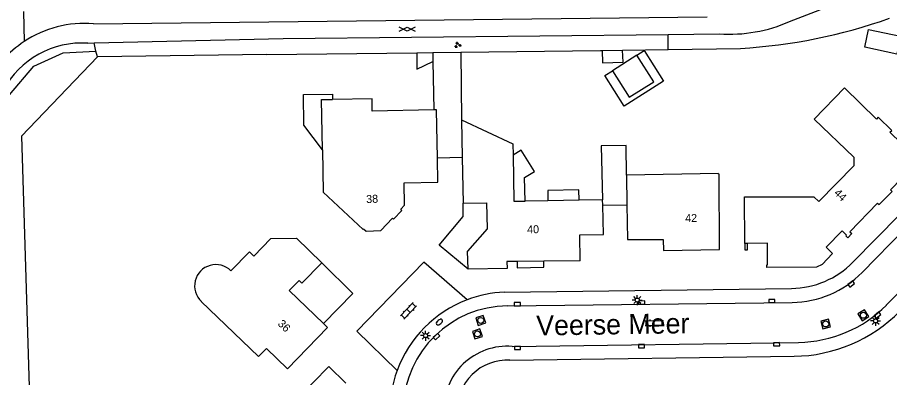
# Model space of a CAD drawing. Extents: x 128999 to 131010, y 395498 to 399007.
# Drawn here: x 130797.9 to 130906.8, y 395862.2 to 395907.2 of the extents above; entities that cross this region are included whole.
import ezdxf

# ---------------------------------------------------------------- set-up
doc = ezdxf.new("R2010")
doc.units = 0
for name, color, linetype in [('gg-afsc-hekwerk', 7, 'Continuous'), ('gg-afsc-muur', 7, 'Continuous'), ('gg-anno-huisnummerreeks BGT', 7, 'Continuous'), ('gg-anno-openbare ruimte label', 7, 'Continuous'), ('gg-bbg-gedigitaliseerde bebouwing', 7, 'Continuous'), ('gg-bbg-gedigitaliseerde bijgebouw', 7, 'Continuous'), ('gg-bbg-hoofdgebouw', 7, 'Continuous'), ('gg-bbg-luifel en loopbrug', 7, 'Continuous'), ('gg-knt-verharding', 7, 'Continuous'), ('gt-grn-groengrens', 7, 'Continuous'), ('gt-symb-brandkraan', 7, 'Continuous'), ('gt-symb-gesloten verharding', 7, 'Continuous'), ('gt-symb-groenvak', 7, 'Continuous'), ('gt-symb-klinker verharding', 7, 'Continuous'), ('gt-symb-kolk', 7, 'Continuous'), ('gt-symb-lichtmast', 7, 'Continuous'), ('gt-symb-rioolschacht', 7, 'Continuous')]:
    doc.layers.add(name, color=color, linetype=linetype)

# ---------------------------------------------------------------- blocks, each defined once
blk = doc.blocks.new('gt0-GRVAK')
at = {"layer": 'gt-symb-groenvak'}
for p, q in [((-0.11, 0.19), (-0.23, 0.24)), ((-0.18, 0.15), (0.09, 0.15)), ((-0.09, 0.21), (-0.16, 0.32)), ((-0.05, 0.21), (-0.05, 0.39)), ((0, 0.21), (0.06, 0.32)), ((0.01, 0.19), (0.13, 0.24)), ((0.26, -0.05), (0.2, 0.06)), ((0.31, -0.05), (0.31, 0.13)), ((0.35, -0.05), (0.41, 0.06)), ((-0.24, -0.23), (-0.36, -0.18)), ((-0.32, -0.26), (-0.05, -0.26)), ((-0.23, -0.21), (-0.29, -0.1)), ((-0.18, -0.2), (-0.18, -0.02)), ((-0.14, -0.21), (-0.07, -0.1)), ((-0.12, -0.23), (0, -0.18)), ((0.24, -0.07), (0.12, -0.02)), ((0.17, -0.11), (0.44, -0.11)), ((0.37, -0.07), (0.49, -0.02))]:
    blk.add_line(p, q, dxfattribs=at)
blk = doc.blocks.new('gt0-GESVH1')
at = {"layer": 'gt-symb-gesloten verharding'}
for p, q in [((-0.99, -0.26), (0.01, 0.24)), ((0.01, -0.26), (-0.99, 0.24)), ((0.01, 0.24), (1.01, -0.26)), ((1.01, 0.24), (0.01, -0.26))]:
    blk.add_line(p, q, dxfattribs=at)
blk = doc.blocks.new('gt0-RS')
at = {"layer": 'gt-symb-rioolschacht'}
blk.add_lwpolyline([(-0.5, -0.5), (0.5, -0.5), (0.5, 0.5), (-0.5, 0.5)], close=True, dxfattribs=at)
blk.add_circle((0, 0), 0.375, dxfattribs=at)
blk = doc.blocks.new('gt0-KOLK')
at = {"layer": 'gt-symb-kolk'}
blk.add_lwpolyline([(0, 0), (0.38, 0), (0.38, 0.4), (-0.38, 0.4), (-0.38, 0), (0, 0)], dxfattribs=at)
blk = doc.blocks.new('gt0-LMAST')
at = {"layer": 'gt-symb-lichtmast'}
for p, q in [((-0.18, 0.17), (-0.45, 0.44)), ((-0.01, 0.25), (-0.01, 0.62)), ((0.17, 0.17), (0.44, 0.44)), ((-0.26, 0), (-0.63, 0)), ((-0.18, -0.18), (-0.45, -0.45)), ((-0.01, -0.25), (-0.01, -0.63)), ((0.44, -0.45), (0.17, -0.18)), ((0.24, 0), (0.62, 0))]:
    blk.add_line(p, q, dxfattribs=at)
blk.add_circle((-0.01, 0), 0.25, dxfattribs=at)
blk = doc.blocks.new('gt0-KL1')
at = {"layer": 'gt-symb-klinker verharding'}
for p, q in [((-1.15, 0.3), (1.15, 0.3)), ((-1, -0.3), (-1, 0.3)), ((-0.5, 0.3), (-0.5, 0.45)), ((0, -0.3), (0, 0.3)), ((0.5, 0.3), (0.5, 0.45)), ((1, -0.3), (1, 0.3)), ((-1.15, -0.3), (1.15, -0.3)), ((-0.5, -0.45), (-0.5, -0.3)), ((0.5, -0.45), (0.5, -0.3))]:
    blk.add_line(p, q, dxfattribs=at)
blk = doc.blocks.new('gt0-BR')
at = {"layer": 'gt-symb-brandkraan'}
for centre, radius, start, end in [((-0.24, 0), 0.206, 107.5669, 252.4331), ((0.6, -2.66), 3, 106.892, 107.5669), ((0, -0.69), 0.938, 73.108, 106.892), ((-0.6, -2.66), 3, 72.4331, 73.108), ((0.24, 0), 0.206, 287.567, 72.4331), ((0.6, 2.66), 3, 252.4331, 253.108), ((0, 0.69), 0.938, 253.108, 286.8921), ((-0.6, 2.66), 3, 286.8921, 287.567)]:
    blk.add_arc(centre, radius, start, end, dxfattribs=at)

msp = doc.modelspace()

# ---------------------------------------------------------------- linework, layer by layer
at = {"layer": 'gg-afsc-hekwerk'}
for p, q in [((130829.04, 395902.55), (130807.85, 395902.25)), ((130870.72, 395903.06), (130870.93, 395903.07)), ((130873.49, 395903.1), (130879.19, 395903.18)), ((130879.19, 395903.18), (130888.21, 395903.32))]:
    msp.add_line(p, q, dxfattribs=at)
msp.add_lwpolyline([(130807.85, 395902.25), (130798.36, 395892.34), (130799.36, 395859.62)], dxfattribs=at)
msp.add_arc((130884.25, 395970.81), 67.61, 273.3578, 289.521, dxfattribs=at)
at = {"layer": 'gg-afsc-muur'}
for p, q in [((130829.04, 395902.55), (130847.75, 395902.78)), ((130853.28, 395902.85), (130870.72, 395903.06))]:
    msp.add_line(p, q, dxfattribs=at)
msp.add_lwpolyline([(130888.76, 395878.92), (130888.77, 395878.14), (130889.09, 395878.14), (130889.09, 395878.92)], dxfattribs=at)
at = {"layer": 'gg-bbg-gedigitaliseerde bebouwing'}
for p, q in [((130853.37, 395894.39), (130853.42, 395889.67)), ((130853.42, 395889.67), (130853.54, 395883.97)), ((130902.36, 395888.65), (130898, 395884.16)), ((130873.97, 395887.47), (130874.03, 395883.78)), ((130864.15, 395884.28), (130861.29, 395884.24)), ((130868.05, 395884.33), (130864.15, 395884.28)), ((130870.99, 395884.38), (130868.05, 395884.33)), ((130871.01, 395883.73), (130870.99, 395884.38)), ((130871.1, 395880.07), (130871.01, 395883.73)), ((130874.03, 395883.78), (130874.11, 395879.42)), ((130827.99, 395864.79), (130820.84, 395871.68))]:
    msp.add_line(p, q, dxfattribs=at)
for points in [[(130905.44, 395894.72), (130905.21, 395894.48), (130901.2, 395898.37), (130897.43, 395894.49), (130902.36, 395889.7), (130902.36, 395888.65)], [(130836, 395890.63), (130835.87, 395896.91), (130837.23, 395896.94)], [(130853.37, 395894.39), (130859.77, 395891.38), (130859.8, 395889.97)], [(130859.8, 395889.97), (130859.91, 395884.22), (130861.29, 395884.24)], [(130885.61, 395878.17), (130885.53, 395887.61), (130885.48, 395887.61), (130885.48, 395887.66), (130873.97, 395887.47)], [(130853.54, 395883.97), (130856.49, 395884.03), (130856.56, 395880.78), (130854.09, 395877.95)], [(130888.71, 395884.78), (130897.36, 395884.78), (130898, 395884.16)], [(130824.53, 395875.51), (130826.84, 395877.88), (130827.4, 395877.34), (130829.51, 395879.55), (130832.72, 395879.6)]]:
    msp.add_lwpolyline(points, dxfattribs=at)
msp.add_arc((130822.66, 395873.63), 2.66, 45.2051, 226.9895, dxfattribs=at)
at = {"layer": 'gg-bbg-gedigitaliseerde bijgebouw'}
msp.add_line((130875.28, 395902.47), (130872.21, 395900.53), dxfattribs=at)
for points in [[(130903.75, 395903.45), (130904.22, 395905.68), (130908.22, 395904.85), (130907.75, 395902.61), (130903.75, 395903.45)], [(130872.21, 395900.53), (130874.32, 395897.2), (130877.39, 395899.14), (130875.28, 395902.47)]]:
    msp.add_lwpolyline(points, dxfattribs=at)
at = {"layer": 'gg-bbg-hoofdgebouw'}
for p, q in [((130888.76, 395878.92), (130888.71, 395884.78)), ((130832.72, 395879.6), (130835.88, 395876.51)), ((130889.09, 395878.92), (130888.76, 395878.92)), ((130854.18, 395875.74), (130854.09, 395877.95)), ((130863.64, 395876.73), (130860.3, 395876.68)), ((130868.16, 395876.78), (130863.64, 395876.73))]:
    msp.add_line(p, q, dxfattribs=at)
for points in [[(130849.88, 395895.64), (130842.2, 395895.49), (130842.18, 395897.01), (130837.23, 395896.94)], [(130850.34, 395889.61), (130850.22, 395895.64), (130849.88, 395895.64)], [(130901.89, 395880.4), (130905.35, 395883.99), (130905.56, 395883.79), (130907.17, 395885.42), (130906.95, 395885.63), (130909.79, 395888.54), (130909.63, 395888.68), (130908.84, 395888.68), (130908.83, 395889.89), (130909.62, 395889.89), (130909.77, 395890.04), (130906.89, 395892.83), (130907.12, 395893.07), (130905.44, 395894.72)], [(130836, 395890.63), (130836.05, 395885.36), (130841.07, 395880.69), (130841.12, 395880.75), (130841.42, 395880.48), (130843.28, 395880.54), (130844.72, 395882.08), (130844.86, 395881.95), (130845.91, 395883.07), (130845.76, 395883.21), (130846.24, 395883.7), (130846.17, 395886.51), (130850.4, 395886.6), (130850.34, 395889.61)], [(130868.16, 395876.78), (130868.12, 395880.03), (130871.1, 395880.07)], [(130901.89, 395880.4), (130902.12, 395880.16), (130901.62, 395879.65), (130901.37, 395879.9), (130901.45, 395879.98), (130900.91, 395880.51), (130898.91, 395878.46), (130899.7, 395877.66), (130898.43, 395876.3), (130897.71, 395875.99)], [(130874.11, 395879.42), (130878.54, 395879.43), (130878.58, 395878.06), (130885.61, 395878.17)], [(130897.71, 395875.99), (130891.49, 395875.94), (130891.49, 395876.27), (130891.61, 395876.27), (130891.59, 395878.95), (130889.09, 395878.92)], [(130835.88, 395876.51), (130833.41, 395873.98), (130833.05, 395874.32), (130831.82, 395873.04), (130836.1, 395868.93)], [(130860.3, 395876.68), (130859.03, 395876.67), (130859.04, 395875.8), (130854.18, 395875.74)], [(130836.1, 395868.93), (130836.62, 395868.43), (130831.6, 395863.26), (130828.98, 395865.8), (130827.99, 395864.79)]]:
    msp.add_lwpolyline(points, dxfattribs=at)
at = {"layer": 'gg-bbg-luifel en loopbrug'}
for p, q in [((130847.75, 395902.78), (130849.75, 395902.8)), ((130849.75, 395902.8), (130853.28, 395902.85)), ((130849.75, 395902.8), (130849.77, 395901.69)), ((130853.28, 395902.85), (130853.37, 395894.39)), ((130870.93, 395903.07), (130873.49, 395903.1)), ((130849.77, 395901.69), (130849.88, 395895.64)), ((130853.42, 395889.67), (130850.34, 395889.61)), ((130871.01, 395883.73), (130874.03, 395883.78))]:
    msp.add_line(p, q, dxfattribs=at)
for points in [[(130847.75, 395902.78), (130847.79, 395900.72), (130849.77, 395901.69)], [(130870.93, 395903.07), (130870.98, 395901.5), (130873.55, 395901.59), (130873.49, 395903.1)], [(130875.28, 395902.47), (130876.17, 395903.04), (130878.6, 395899.21), (130873.68, 395896.1), (130871.26, 395899.92), (130872.21, 395900.53)], [(130836, 395890.63), (130833.66, 395893.74), (130833.61, 395897.57), (130837.22, 395897.61), (130837.23, 395896.94)], [(130861.29, 395884.24), (130861.23, 395887.17), (130862.46, 395887.94), (130860.8, 395890.6), (130859.8, 395889.97)], [(130873.97, 395887.47), (130873.91, 395891.17), (130870.82, 395891.12), (130870.99, 395884.38)], [(130868.05, 395884.33), (130868.03, 395885.62), (130864.12, 395885.55), (130864.15, 395884.28)], [(130854.18, 395875.74), (130850.55, 395878.7), (130853.58, 395882.3), (130853.54, 395883.97)], [(130835.88, 395876.51), (130839.78, 395872.68), (130836.1, 395868.93)], [(130860.3, 395876.68), (130860.32, 395875.89), (130863.65, 395875.95), (130863.64, 395876.73)], [(130838.91, 395861.49), (130836.78, 395863.56), (130832.87, 395859.54), (130834.99, 395857.47)]]:
    msp.add_lwpolyline(points, dxfattribs=at)
at = {"layer": 'gg-knt-verharding'}
for p, q in [((130894.36, 395906.67), (130903.75, 395910.33)), ((130807.36, 395906.39), (130884.04, 395907.27)), ((130879.17, 395905.07), (130885.59, 395905.13)), ((130806.64, 395903.97), (130807.44, 395903.99)), ((130903.41, 395875.3), (130908.72, 395880.71)), ((130906.44, 395871.23), (130912.33, 395877.16)), ((130858.71, 395872.86), (130894.59, 395873.3)), ((130859.14, 395871.13), (130894.67, 395871.57)), ((130859.67, 395866.07), (130895.46, 395866.57)), ((130859.41, 395864.33), (130894.91, 395864.83))]:
    msp.add_line(p, q, dxfattribs=at)
for points in [[(130807.44, 395903.99), (130831.07, 395904.56), (130879.17, 395905.07)], [(130902.26, 395876.58), (130910.99, 395885.48), (130918.09, 395892.81)], [(130854.06, 395871.89), (130848.63, 395876.58), (130840.26, 395867.98), (130845.3, 395863.04)]]:
    msp.add_lwpolyline(points, dxfattribs=at)
for centre, radius, start, end in [((130806.25, 395892.72), 13.72, 85.3839, 123.4647), ((130886.84, 395923.78), 18.69, 266.1683, 293.7172), ((130806.26, 395892.72), 13.72, 123.4836, 152.7203), ((130805.95, 395892.8), 11.19, 86.4746, 151.6318), ((130894.45, 395884.25), 10.94, 270.7206, 315.516), ((130894.52, 395884.03), 12.46, 270.7135, 315.5141), ((130859.41, 395857.88), 15, 92.672, 110.9029), ((130859.41, 395857.85), 15.03, 110.8661, 159.7976), ((130859.22, 395857.96), 13.17, 90.3847, 177.9885), ((130895.25, 395882.34), 15.77, 270.7853, 315.2259), ((130894.65, 395883.81), 18.98, 270.81, 315.2783), ((130859.08, 395858.13), 7.96, 85.7092, 181.8751), ((130859.01, 395858.2), 6.14, 86.3002, 183.4094), ((130859.4, 395857.84), 15.02, 159.7743, 180.7994)]:
    msp.add_arc(centre, radius, start, end, dxfattribs=at)
at = {"layer": 'gt-grn-groengrens'}
for p, q in [((130798.63, 395907.92), (130798.69, 395904.16)), ((130879.19, 395903.18), (130879.17, 395905.07)), ((130807.67, 395902.98), (130807.44, 395903.99)), ((130807.85, 395902.25), (130807.67, 395902.98))]:
    msp.add_line(p, q, dxfattribs=at)
msp.add_lwpolyline([(130800.1, 395715.45), (130793.95, 395886.12), (130793.99, 395888.96), (130794.71, 395892.91), (130796.85, 395897.52), (130799.92, 395901.1), (130803.59, 395902.78), (130807.67, 395902.98)], dxfattribs=at)

# ---------------------------------------------------------------- block references
at = {"layer": 'gt-symb-brandkraan', "rotation": -142.14510603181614}
msp.add_blockref('gt0-BR', (130850.6, 395869.11), dxfattribs=at)
at = {"layer": 'gt-symb-gesloten verharding', "rotation": 0.4583564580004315}
msp.add_blockref('gt0-GESVH1', (130846.54, 395905.73), dxfattribs=at)
at = {"layer": 'gt-symb-groenvak'}
msp.add_blockref('gt0-GRVAK', (130852.87, 395903.73), dxfattribs=at)
at = {"layer": 'gt-symb-klinker verharding'}
for p, rotation in [((130846.73, 395870.51), -134.23070360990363), ((130877.44, 395868.98), 0.7448031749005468)]:
    msp.add_blockref('gt0-KL1', p, dxfattribs=dict(at, rotation=rotation))
at = {"layer": 'gt-symb-kolk'}
for p, rotation in [((130901.93, 395874.02), -143.57682169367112), ((130860.33, 395871.15), 0.7448031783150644), ((130875.87, 395871.34), 0.687516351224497), ((130892.13, 395871.54), 0.6302281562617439), ((130905.2, 395870.14), -141.1701750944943), ((130850.09, 395867.43), -136.21542825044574), ((130860.35, 395866.07), -179.88540859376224), ((130875.85, 395866.29), -179.14062775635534), ((130892.73, 395866.53), -179.1979114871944)]:
    msp.add_blockref('gt0-KOLK', p, dxfattribs=dict(at, rotation=rotation))
at = {"layer": 'gt-symb-lichtmast'}
for p in [(130875.32, 395871.86), (130905.1, 395869.25), (130848.87, 395867.41)]:
    msp.add_blockref('gt0-LMAST', p, dxfattribs=at)
at = {"layer": 'gt-symb-rioolschacht'}
for p, rotation in [((130855.76, 395869.31), 18.181268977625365), ((130903.57, 395869.96), 31.750196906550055), ((130898.86, 395868.87), 15.300324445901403), ((130855.35, 395867.63), 18.670583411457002)]:
    msp.add_blockref('gt0-RS', p, dxfattribs=dict(at, rotation=rotation))

# ---------------------------------------------------------------- texts
at = {"layer": 'gg-anno-huisnummerreeks BGT'}
for s, rotation, p in [('44', 316.1, (130899.83, 395885.15)), ('38', 1.9, (130841.46, 395883.98)), ('42', 0.9, (130881.31, 395881.6)), ('40', 0.7, (130861.56, 395880.2)), ('36', 315.9, (130830.32, 395868.8))]:
    msp.add_text(s, height=1, rotation=rotation, dxfattribs=at).set_placement(p)
at = {"layer": 'gg-anno-openbare ruimte label'}
msp.add_text('Veerse Meer', height=2.5, rotation=0.9, dxfattribs=at).set_placement((130862.71, 395867.42))

doc.saveas('drawing.dxf')
